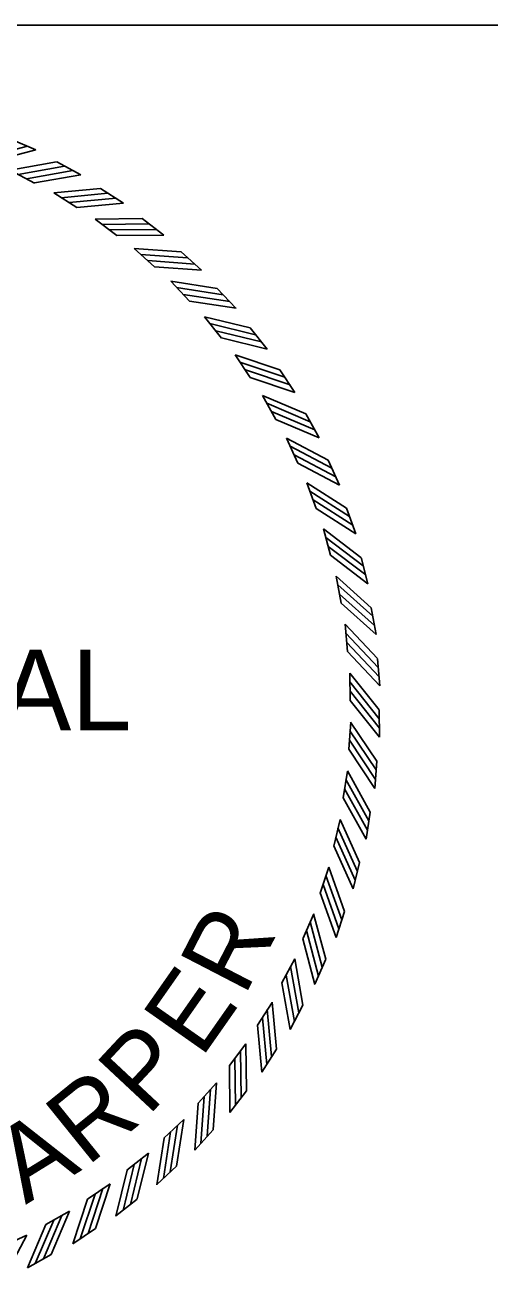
# Model space of a CAD drawing. Extents: x 16 to 1228740, y 11 to 152440.
# Drawn here: x 17.7979 to 17.8623, y 10.8254 to 10.9986 of the extents above; entities that cross this region are included whole.
import ezdxf

# ---------------------------------------------------------------- set-up
doc = ezdxf.new("R2010")
doc.units = 0
doc.layers.add('R_No Plot', color=7, linetype='Continuous')
doc.layers.add('STAMP_FRED', color=7, linetype='Continuous')

msp = doc.modelspace()

# ---------------------------------------------------------------- linework, layer by layer
at = {"layer": 'R_No Plot'}
msp.add_line((17.888, 10.99864), (17.47349, 10.99864), dxfattribs=at)
at = {"layer": 'STAMP_FRED'}
for p, q in [((17.79591, 10.98283), (17.79938, 10.98135)), ((17.80228, 10.97968), (17.80561, 10.97791)), ((17.79585, 10.97854), (17.79919, 10.97677)), ((17.80187, 10.9754), (17.80505, 10.97337)), ((17.80836, 10.97601), (17.81154, 10.97398)), ((17.8076, 10.97178), (17.81061, 10.96949)), ((17.81413, 10.97185), (17.81712, 10.96956)), ((17.81302, 10.9677), (17.81582, 10.96517)), ((17.81952, 10.96723), (17.82232, 10.9647)), ((17.81808, 10.96319), (17.82066, 10.96043)), ((17.82452, 10.96218), (17.8271, 10.95943)), ((17.82275, 10.95827), (17.8251, 10.95531)), ((17.82909, 10.95673), (17.83143, 10.95378)), ((17.827, 10.95298), (17.82909, 10.94984)), ((17.83319, 10.95093), (17.83528, 10.94779)), ((17.83079, 10.94737), (17.83262, 10.94406)), ((17.83679, 10.94481), (17.83862, 10.94151)), ((17.83411, 10.94145), (17.83566, 10.93801)), ((17.83988, 10.93841), (17.84143, 10.93497)), ((17.83694, 10.93529), (17.8382, 10.93172)), ((17.84243, 10.93177), (17.84369, 10.92822)), ((17.83924, 10.92891), (17.8402, 10.92525)), ((17.84443, 10.92495), (17.84538, 10.92131)), ((17.841, 10.92236), (17.84166, 10.91864)), ((17.84585, 10.91799), (17.8465, 10.91428)), ((17.84222, 10.91569), (17.84257, 10.91193)), ((17.84669, 10.91093), (17.84704, 10.90718)), ((17.84289, 10.90894), (17.84292, 10.90516)), ((17.84695, 10.90383), (17.84698, 10.90006)), ((17.843, 10.90216), (17.84272, 10.89839)), ((17.84254, 10.89539), (17.84195, 10.89166)), ((17.84662, 10.89673), (17.84634, 10.89297)), ((17.84153, 10.88869), (17.84064, 10.88501)), ((17.8457, 10.88969), (17.84512, 10.88596)), ((17.83997, 10.88209), (17.83877, 10.8785)), ((17.84421, 10.88274), (17.84332, 10.87908)), ((17.83787, 10.87564), (17.83638, 10.87216)), ((17.84215, 10.87594), (17.84096, 10.87236)), ((17.83524, 10.86939), (17.83347, 10.86605)), ((17.83953, 10.86933), (17.83805, 10.86587)), ((17.8321, 10.86337), (17.83007, 10.86019)), ((17.83638, 10.86296), (17.83461, 10.85963)), ((17.82848, 10.85764), (17.82619, 10.85464)), ((17.83271, 10.85688), (17.83068, 10.8537)), ((17.8244, 10.85222), (17.82187, 10.84942)), ((17.82855, 10.85112), (17.82626, 10.84812)), ((17.81989, 10.84716), (17.81713, 10.84458)), ((17.82393, 10.84572), (17.8214, 10.84292)), ((17.81497, 10.84249), (17.81201, 10.84014)), ((17.81888, 10.84072), (17.81613, 10.83814)), ((17.80968, 10.83824), (17.80654, 10.83615)), ((17.81343, 10.83615), (17.81048, 10.83381)), ((17.80407, 10.83445), (17.80076, 10.83262)), ((17.80763, 10.83205), (17.80449, 10.82996)), ((17.79815, 10.83113), (17.79471, 10.82958)), ((17.80151, 10.82845), (17.79821, 10.82662))]:
    msp.add_line(p, q, dxfattribs=at)
for points in [[(17.79192, 10.98019), (17.79823, 10.98185)], [(17.79307, 10.97968), (17.79938, 10.98135)], [(17.79585, 10.97854), (17.80227, 10.97968)], [(17.79692, 10.97796), (17.80334, 10.9791)], [(17.79809, 10.97737), (17.80451, 10.97851)], [(17.79919, 10.97678), (17.80561, 10.97791)], [(17.80186, 10.9754), (17.80836, 10.97601)], [(17.80288, 10.97474), (17.80937, 10.97535)], [(17.804, 10.97406), (17.81049, 10.97466)], [(17.80505, 10.97337), (17.81154, 10.97398)], [(17.8076, 10.97178), (17.81412, 10.97185)], [(17.80855, 10.97104), (17.81508, 10.97111)], [(17.80961, 10.97027), (17.81613, 10.97033)], [(17.8106, 10.9695), (17.81713, 10.96956)], [(17.81301, 10.9677), (17.81952, 10.96723)], [(17.81391, 10.96688), (17.82041, 10.96641)], [(17.8149, 10.96603), (17.8214, 10.96555)], [(17.81582, 10.96517), (17.82233, 10.9647)], [(17.81807, 10.96319), (17.82452, 10.96218)], [(17.81889, 10.9623), (17.82534, 10.96129)], [(17.81981, 10.96136), (17.82626, 10.96035)], [(17.82066, 10.96044), (17.82711, 10.95943)], [(17.82274, 10.95827), (17.82908, 10.95674)], [(17.82349, 10.95731), (17.82983, 10.95578)], [(17.82433, 10.95631), (17.83066, 10.95477)], [(17.8251, 10.95532), (17.83144, 10.95378)], [(17.82699, 10.95299), (17.83318, 10.95093)], [(17.82766, 10.95197), (17.83385, 10.94992)], [(17.82841, 10.9509), (17.8346, 10.94884)], [(17.82909, 10.94985), (17.83528, 10.94779)], [(17.83079, 10.94737), (17.83679, 10.94481)], [(17.83137, 10.9463), (17.83737, 10.94374)], [(17.83203, 10.94517), (17.83803, 10.94261)], [(17.83262, 10.94406), (17.83862, 10.94151)], [(17.83411, 10.94146), (17.83988, 10.93841)], [(17.8346, 10.94034), (17.84037, 10.9373)], [(17.83516, 10.93916), (17.84093, 10.93612)], [(17.83567, 10.93801), (17.84143, 10.93497)], [(17.83693, 10.93529), (17.84243, 10.93178)], [(17.83732, 10.93414), (17.84282, 10.93063)], [(17.83779, 10.93292), (17.84329, 10.9294)], [(17.8382, 10.93173), (17.84369, 10.92822)], [(17.83923, 10.92891), (17.84442, 10.92496)], [(17.83953, 10.92773), (17.84472, 10.92378)], [(17.83989, 10.92647), (17.84508, 10.92252)], [(17.8402, 10.92526), (17.84539, 10.9213)], [(17.841, 10.92236), (17.84584, 10.91799)], [(17.8412, 10.92117), (17.84604, 10.9168)], [(17.84146, 10.91988), (17.8463, 10.91551)], [(17.84166, 10.91864), (17.84651, 10.91427)], [(17.84222, 10.91569), (17.84669, 10.91094)], [(17.84232, 10.91448), (17.84679, 10.90973)], [(17.84247, 10.91318), (17.84694, 10.90843)], [(17.84257, 10.91193), (17.84704, 10.90718)], [(17.84289, 10.90894), (17.84695, 10.90384)], [(17.84289, 10.90773), (17.84695, 10.90262)], [(17.84293, 10.90642), (17.84699, 10.90131)], [(17.84293, 10.90517), (17.84699, 10.90006)], [(17.84289, 10.90095), (17.84652, 10.89553)], [(17.84299, 10.90216), (17.84662, 10.89674)], [(17.84283, 10.89965), (17.84645, 10.89422)], [(17.84272, 10.89839), (17.84634, 10.89297)], [(17.84254, 10.8954), (17.8457, 10.88969)], [(17.84234, 10.8942), (17.8455, 10.8885)], [(17.84216, 10.8929), (17.84533, 10.8872)], [(17.84196, 10.89166), (17.84512, 10.88596)], [(17.84153, 10.88869), (17.84421, 10.88274)], [(17.84123, 10.88752), (17.84391, 10.88157)], [(17.84064, 10.88502), (17.84332, 10.87907)], [(17.84095, 10.88624), (17.84363, 10.88029)], [(17.83997, 10.88209), (17.84215, 10.87594)], [(17.83957, 10.88094), (17.84175, 10.8748)], [(17.83878, 10.87851), (17.84096, 10.87236)], [(17.83919, 10.87969), (17.84137, 10.87355)], [(17.83786, 10.87564), (17.83953, 10.86934)], [(17.83689, 10.87332), (17.83855, 10.86701)], [(17.83738, 10.87453), (17.83904, 10.86823)], [(17.83638, 10.87217), (17.83805, 10.86586)], [(17.83524, 10.86939), (17.83638, 10.86297)], [(17.83466, 10.86833), (17.8358, 10.8619)], [(17.83348, 10.86605), (17.83461, 10.85963)], [(17.83407, 10.86715), (17.83521, 10.86073)], [(17.8321, 10.86338), (17.83271, 10.85688)], [(17.83076, 10.86124), (17.83136, 10.85475)], [(17.83144, 10.86236), (17.83204, 10.85587)], [(17.83007, 10.86019), (17.83068, 10.8537)], [(17.82848, 10.85764), (17.82855, 10.85112)], [(17.82697, 10.85563), (17.82703, 10.84911)], [(17.82774, 10.85669), (17.82781, 10.85016)], [(17.8262, 10.85464), (17.82626, 10.84811)], [(17.8244, 10.85223), (17.82393, 10.84572)], [(17.82272, 10.85034), (17.82225, 10.84384)], [(17.82358, 10.85134), (17.82311, 10.84483)], [(17.82187, 10.84942), (17.8214, 10.84291)], [(17.81989, 10.84717), (17.81888, 10.84072)], [(17.81806, 10.84543), (17.81705, 10.83898)], [(17.819, 10.84635), (17.81799, 10.8399)], [(17.81714, 10.84458), (17.81613, 10.83813)], [(17.81401, 10.84175), (17.81248, 10.83541)], [(17.81497, 10.8425), (17.81344, 10.83616)], [(17.81202, 10.84014), (17.81048, 10.8338)], [(17.81301, 10.84092), (17.81147, 10.83458)], [(17.80969, 10.83825), (17.80763, 10.83206)], [(17.8076, 10.83683), (17.80554, 10.83064)], [(17.80867, 10.83759), (17.80662, 10.83139)], [(17.80655, 10.83615), (17.80449, 10.82996)], [(17.80187, 10.83321), (17.79931, 10.82721)], [(17.803, 10.83387), (17.80044, 10.82787)], [(17.80407, 10.83445), (17.80151, 10.82845)], [(17.80076, 10.83262), (17.79821, 10.82662)], [(17.79816, 10.83113), (17.79511, 10.82536)]]:
    msp.add_lwpolyline(points, dxfattribs=at)

# ---------------------------------------------------------------- texts
msp.add_text('PROFESSIONAL', height=0.0111934, dxfattribs=at).set_placement((17.69618, 10.901))
for s, rotation, p in [('R', 62.6418, (17.82825, 10.86405)), ('E', 54.981, (17.82229, 10.85549)), ('P', 46.9554, (17.81488, 10.84746)), ('R', 38.9298, (17.80643, 10.84054)), ('A', 31.6338, (17.79797, 10.83533))]:
    msp.add_text(s, height=0.01042, rotation=rotation, dxfattribs=at).set_placement(p)

doc.saveas('drawing.dxf')
